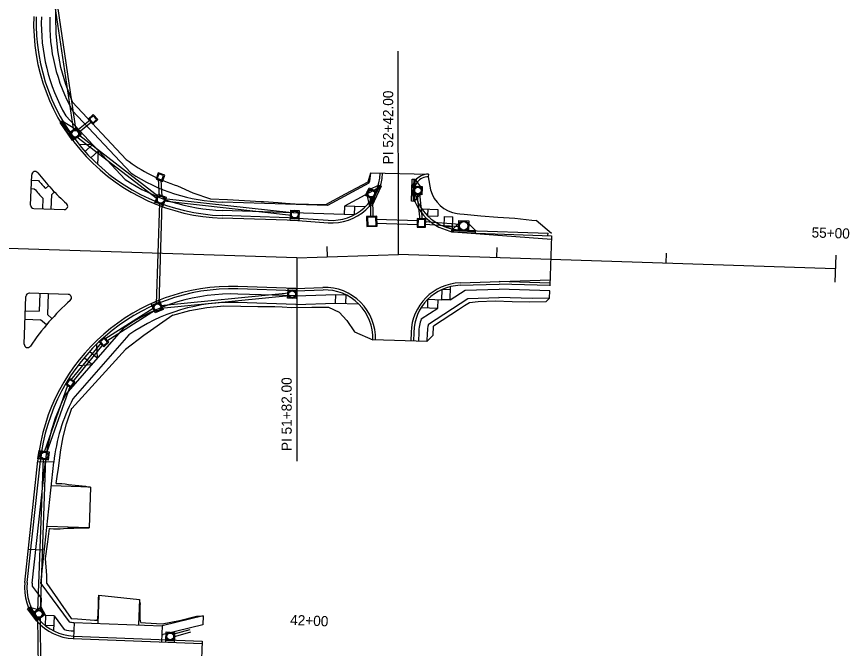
# Model space of a CAD drawing. Extents: x 979959 to 994833, y 1835619 to 1845316.
# Drawn here: x 992513.5 to 993004.9, y 1843149.5 to 1843522.3 of the extents above; entities that cross this region are included whole.
import ezdxf

# ---------------------------------------------------------------- set-up
doc = ezdxf.new("R2010")
doc.units = 0
for name, color, linetype in [('R_Drainage', 7, 'Continuous'), ('R_Horz Alg', 7, 'Continuous'), ('R_Horz Alg Annot', 7, 'Continuous'), ('R_Horz Alg Stationing', 7, 'Continuous'), ('R_Proposed Const Limits', 7, 'Continuous'), ('R_Proposed Road', 7, 'Continuous')]:
    doc.layers.add(name, color=color, linetype=linetype)

msp = doc.modelspace()

# ---------------------------------------------------------------- linework, layer by layer
at = {"layer": 'R_Drainage'}
for p, q in [((992526.47, 1843592.92), (992547.02, 1843454.89)), ((992527.95, 1843593.14), (992548.51, 1843455.11)), ((992540.06, 1843460.44), (992547.38, 1843449.69)), ((992540.47, 1843460.72), (992549.34, 1843455.3)), ((992556.85, 1843461.25), (992549.01, 1843454.92)), ((992557.86, 1843460.13), (992549.95, 1843453.75)), ((992548.7, 1843456.64), (992551.51, 1843452.51)), ((992549.97, 1843452.63), (992597.53, 1843415.96)), ((992549.05, 1843451.44), (992596.61, 1843414.78)), ((992597.04, 1843426.47), (992597.68, 1843416.04)), ((992598.58, 1843425.91), (992599.17, 1843416.13)), ((992727.32, 1843422.9), (992721.65, 1843420.09)), ((992722.28, 1843410.9), (992727.77, 1843422.69)), ((992748, 1843426.28), (992747.58, 1843413.29)), ((992748.5, 1843426.27), (992752.29, 1843421.2)), ((992719.44, 1843416.64), (992721.55, 1843421.17)), ((992748.08, 1843413.27), (992752.19, 1843418.08)), ((992749.74, 1843417.78), (992751.4, 1843402.56)), ((992751.24, 1843417.94), (992752.92, 1843402.51)), ((992752.87, 1843422.12), (992752.71, 1843417.12)), ((992597.1, 1843417.47), (992601.77, 1843415.68)), ((992675.72, 1843404.94), (992600.3, 1843413.29)), ((992675.72, 1843404.94), (992600.3, 1843413.29)), ((992675.88, 1843406.43), (992600.46, 1843414.78)), ((992675.88, 1843406.43), (992600.46, 1843414.78)), ((992721.82, 1843411.12), (992720.33, 1843417.26)), ((992722.05, 1843415.98), (992722.3, 1843403.92)), ((992723.55, 1843416.01), (992723.8, 1843403.98)), ((992597.73, 1843412.41), (992595.94, 1843352.57)), ((992597.73, 1843412.41), (992595.94, 1843352.57)), ((992599.23, 1843412.36), (992597.44, 1843352.53)), ((992599.23, 1843412.36), (992597.44, 1843352.53)), ((992675.23, 1843408.07), (992680.23, 1843407.89)), ((992750.42, 1843401.84), (992725.56, 1843402.62)), ((992750.34, 1843399.34), (992725.65, 1843400.12)), ((992774.9, 1843398.22), (992754.35, 1843399.64)), ((992775, 1843399.71), (992754.4, 1843401.14)), ((992770.25, 1843396.53), (992775.34, 1843401.04)), ((992784.25, 1843396.07), (992779.47, 1843400.91)), ((992770.24, 1843396.03), (992784.23, 1843395.57)), ((992674.14, 1843359.07), (992598.41, 1843351.62)), ((992674.14, 1843359.07), (992598.41, 1843351.62)), ((992674.29, 1843357.58), (992598.56, 1843350.13)), ((992674.29, 1843357.58), (992598.56, 1843350.13)), ((992678.42, 1843355.88), (992673.43, 1843356.15)), ((992594.67, 1843350.34), (992565.63, 1843331.91)), ((992595.47, 1843349.07), (992566.66, 1843330.78)), ((992599.92, 1843349.37), (992595.31, 1843347.42)), ((992563.42, 1843329.88), (992545.33, 1843307.71)), ((992564.44, 1843328.76), (992546.62, 1843306.92)), ((992543.75, 1843305.16), (992529.8, 1843265.3)), ((992545.06, 1843304.36), (992531.21, 1843264.81)), ((992532.69, 1843265.47), (992532.06, 1843260.51)), ((992529.08, 1843261.48), (992525.87, 1843171.69)), ((992530.58, 1843261.43), (992527.37, 1843171.64)), ((992520.65, 1843173.5), (992526.07, 1843166.31)), ((992521.05, 1843173.8), (992527.18, 1843172.24)), ((992527.05, 1843173.31), (992530.06, 1843169.32)), ((992525.83, 1843167.95), (992526.27, 1843128.53)), ((992527.33, 1843167.97), (992527.77, 1843128.47)), ((992601.76, 1843159.14), (992606.76, 1843158.94)), ((992605.74, 1843157.77), (992615.99, 1843160.69)), ((992606.15, 1843156.33), (992616.4, 1843159.25))]:
    msp.add_line(p, q, dxfattribs=at)
for points in [[(992558.38, 1843458.81), (992561.35, 1843461.48), (992558.67, 1843464.46), (992555.7, 1843461.78)], [(992558.41, 1843459.51), (992560.64, 1843461.52), (992558.64, 1843463.75), (992556.41, 1843461.74)], [(992540.47, 1843460.72), (992547.8, 1843449.98), (992546.56, 1843449.13), (992539.23, 1843459.87)], [(992548.7, 1843456.64), (992551.51, 1843452.51), (992547.38, 1843449.69), (992544.57, 1843453.83)], [(992600.88, 1843428.8), (992597.12, 1843430.16), (992595.76, 1843426.4), (992599.52, 1843425.04)], [(992600.24, 1843428.5), (992597.42, 1843429.52), (992596.4, 1843426.7), (992599.22, 1843425.68)], [(992721.82, 1843411.12), (992727.32, 1843422.9), (992728.68, 1843422.26), (992723.18, 1843410.48)], [(992748.5, 1843426.27), (992748.08, 1843413.27), (992746.58, 1843413.32), (992747, 1843426.32)], [(992719.44, 1843416.64), (992721.55, 1843421.17), (992726.08, 1843419.06), (992723.97, 1843414.53)], [(992752.87, 1843422.12), (992752.71, 1843417.12), (992747.71, 1843417.29), (992747.87, 1843422.29)], [(992595.49, 1843413.27), (992600.15, 1843411.47), (992599.62, 1843410.07), (992594.95, 1843411.87)], [(992597.1, 1843417.47), (992601.77, 1843415.68), (992599.97, 1843411.01), (992595.31, 1843412.8)], [(992675.23, 1843408.07), (992680.23, 1843407.89), (992680.05, 1843402.9), (992675.06, 1843403.07)], [(992675.08, 1843403.57), (992680.07, 1843403.4), (992680.02, 1843401.9), (992675.02, 1843402.07)], [(992726, 1843404.55), (992720, 1843404.35), (992720.2, 1843398.35), (992726.2, 1843398.55)], [(992725.51, 1843404.03), (992720.52, 1843403.86), (992720.69, 1843398.87), (992725.68, 1843399.04)], [(992754.96, 1843402.95), (992749.96, 1843403.11), (992749.8, 1843398.11), (992754.8, 1843397.95)], [(992754.44, 1843402.46), (992750.45, 1843402.59), (992750.32, 1843398.6), (992754.31, 1843398.47)], [(992774.43, 1843401.9), (992780.43, 1843401.7), (992780.23, 1843395.7), (992774.24, 1843395.9)], [(992770.25, 1843396.53), (992784.25, 1843396.07), (992784.2, 1843394.57), (992770.2, 1843395.03)], [(992678.42, 1843355.88), (992673.43, 1843356.15), (992673.7, 1843361.14), (992678.69, 1843360.87)], [(992678.66, 1843360.37), (992673.67, 1843360.64), (992673.75, 1843362.14), (992678.74, 1843361.87)], [(992598.16, 1843353.51), (992593.56, 1843351.56), (992592.97, 1843352.94), (992597.57, 1843354.89)], [(992599.92, 1843349.37), (992595.31, 1843347.42), (992593.36, 1843352.02), (992597.96, 1843353.97)], [(992564.91, 1843327.51), (992567.86, 1843330.21), (992565.16, 1843333.16), (992562.21, 1843330.46)], [(992564.94, 1843328.21), (992567.16, 1843330.24), (992565.13, 1843332.45), (992562.92, 1843330.43)], [(992545.85, 1843303.29), (992547.94, 1843306.7), (992544.53, 1843308.79), (992542.44, 1843305.38)], [(992545.69, 1843303.97), (992547.25, 1843306.53), (992544.7, 1843308.1), (992543.13, 1843305.54)], [(992528.23, 1843266.04), (992527.59, 1843261.08), (992526.1, 1843261.27), (992526.74, 1843266.23)], [(992532.69, 1843265.47), (992532.06, 1843260.51), (992527.1, 1843261.14), (992527.73, 1843266.1)], [(992521.05, 1843173.8), (992526.47, 1843166.61), (992525.27, 1843165.71), (992519.85, 1843172.9)], [(992527.05, 1843173.31), (992530.06, 1843169.32), (992526.07, 1843166.31), (992523.06, 1843170.31)], [(992601.76, 1843159.14), (992606.76, 1843158.94), (992606.57, 1843153.95), (992601.57, 1843154.14)], [(992601.59, 1843154.64), (992606.58, 1843154.45), (992606.53, 1843152.95), (992601.53, 1843153.14)]]:
    msp.add_lwpolyline(points, close=True, dxfattribs=at)
for centre, radius in [((992548.04, 1843453.17), 2.5), ((992548.04, 1843453.17), 2.5), ((992548.04, 1843453.17), 2), ((992548.04, 1843453.17), 2), ((992722.76, 1843417.85), 2.5), ((992722.76, 1843417.85), 2.5), ((992722.76, 1843417.85), 2), ((992722.76, 1843417.85), 2), ((992750.29, 1843419.7), 2.5), ((992750.29, 1843419.7), 2.5), ((992750.29, 1843419.7), 2), ((992750.29, 1843419.7), 2), ((992598.54, 1843414.24), 2.5), ((992598.54, 1843414.24), 2.5), ((992598.54, 1843414.24), 2), ((992598.54, 1843414.24), 2), ((992677.64, 1843405.48), 2.5), ((992677.64, 1843405.48), 2.5), ((992677.64, 1843405.48), 2), ((992677.64, 1843405.48), 2), ((992777.33, 1843398.8), 3), ((992777.33, 1843398.8), 3), ((992777.33, 1843398.8), 2.5), ((992777.33, 1843398.8), 2.5), ((992676.06, 1843358.51), 2.5), ((992676.06, 1843358.51), 2.5), ((992676.06, 1843358.51), 2), ((992676.06, 1843358.51), 2), ((992596.64, 1843350.7), 2.5), ((992596.64, 1843350.7), 2.5), ((992596.64, 1843350.7), 2), ((992596.64, 1843350.7), 2), ((992529.89, 1843263.31), 2.5), ((992529.89, 1843263.31), 2.5), ((992529.89, 1843263.31), 2), ((992529.89, 1843263.31), 2), ((992526.56, 1843169.81), 2.5), ((992526.56, 1843169.81), 2.5), ((992526.56, 1843169.81), 2), ((992526.56, 1843169.81), 2), ((992604.16, 1843156.54), 2.5), ((992604.16, 1843156.54), 2.5), ((992604.16, 1843156.54), 2), ((992604.16, 1843156.54), 2)]:
    msp.add_circle(centre, radius, dxfattribs=at)
at = {"layer": 'R_Horz Alg'}
for p, q in [((992678.8, 1843379.93), (992496.9, 1843385.9)), ((992678.8, 1843379.93), (992738.77, 1843381.96)), ((992996.63, 1843373.5), (992738.77, 1843381.96))]:
    msp.add_line(p, q, dxfattribs=at)
at = {"layer": 'R_Horz Alg Annot'}
for points in [[(992738.77, 1843381.96), (992738.7, 1843501.96)], [(992678.8, 1843379.93), (992678.87, 1843259.93)]]:
    msp.add_lwpolyline(points, dxfattribs=at)
at = {"layer": 'R_Horz Alg Stationing'}
for points in [[(992597.04, 1843388.62), (992596.85, 1843382.62)], [(992696.59, 1843386.54), (992696.79, 1843380.54)], [(992796.93, 1843386.06), (992796.74, 1843380.06)], [(992896.88, 1843382.78), (992896.68, 1843376.78)], [(992996.89, 1843381.49), (992996.36, 1843365.5)]]:
    msp.add_lwpolyline(points, dxfattribs=at)
at = {"layer": 'R_Proposed Const Limits'}
for p, q in [((992546.49, 1843471.84), (992578.15, 1843437.98)), ((992756.47, 1843427.76), (992757.74, 1843420.14)), ((992608.5, 1843422.41), (992617.57, 1843418.38))]:
    msp.add_line(p, q, dxfattribs=at)
for points in [[(992546.49, 1843471.84), (992546.39, 1843472.05), (992542.46, 1843482.19), (992539.58, 1843492.3), (992537.77, 1843502.36), (992536.93, 1843512.4), (992536.66, 1843522.41), (992536.52, 1843532.42), (992536.43, 1843542.43), (992536.26, 1843552.45), (992536.22, 1843554.46), (992536.31, 1843562.45), (992535.91, 1843572.47), (992535.73, 1843577.99), (992535.61, 1843582.49), (992535.74, 1843592.49), (992538.25, 1843608.43)], [(992696, 1843411.44), (992707.64, 1843417.7), (992720.98, 1843424.82), (992722.47, 1843430.02)], [(992617.57, 1843418.38), (992627.91, 1843414.69), (992637.91, 1843414.36), (992647.89, 1843413.73), (992657.88, 1843413.2), (992659.13, 1843413.22), (992667.87, 1843412.55), (992672.25, 1843412.21), (992677.85, 1843411.84), (992677.85, 1843411.84), (992685.73, 1843411.61), (992695.16, 1843411.45), (992696, 1843411.44)], [(992773.55, 1843406.12), (992775.15, 1843405.91), (992777.57, 1843405.68), (992787.54, 1843404.8), (992797.52, 1843404.02), (992807.5, 1843403.33), (992817.47, 1843402.19), (992820.11, 1843401.95)], [(992829.22, 1843394.34), (992820.11, 1843401.95)], [(992827.97, 1843356.1), (992825.9, 1843354.03), (992815.89, 1843353.87), (992805.89, 1843354.06), (992795.89, 1843354.34), (992785.87, 1843353.89), (992780.77, 1843353.46), (992777.89, 1843351.65), (992774.25, 1843349.28), (992769.78, 1843346.36), (992759.59, 1843339.71)], [(992605.65, 1843346.18), (992615.75, 1843348.86), (992625.81, 1843350.7), (992635.85, 1843351.66), (992645.85, 1843351.39), (992655.85, 1843351.26), (992657.1, 1843351.26), (992665.85, 1843351.13), (992670.24, 1843350.95), (992675.84, 1843350.73), (992675.85, 1843350.73), (992687.79, 1843350.83), (992697.21, 1843350.82), (992697.6, 1843350.82)], [(992697.6, 1843350.82), (992703.81, 1843347.92), (992708.41, 1843342.89), (992712.83, 1843336.28), (992723.8, 1843331.55)], [(992605.65, 1843346.18), (992588.49, 1843334.03), (992577.81, 1843325.85), (992545.98, 1843291.08)], [(992755.68, 1843330.48), (992759.41, 1843334.33), (992759.59, 1843339.71)], [(992536.74, 1843246.76), (992537.6, 1843252.22), (992538.13, 1843255.65), (992538.9, 1843262.18), (992539.51, 1843266.63), (992540.51, 1843272.14), (992540.96, 1843274.25), (992542.97, 1843282.06), (992546.04, 1843291.15)], [(992536.74, 1843246.76), (992538.16, 1843246.8), (992540.15, 1843246.71), (992542.15, 1843246.48), (992544.14, 1843246.26), (992546.13, 1843246.04), (992548.13, 1843245.82), (992550.12, 1843245.6), (992552.12, 1843245.38), (992554.11, 1843245.15), (992555.59, 1843244.82), (992557.09, 1843244.55)], [(992531.41, 1843187.85), (992531.27, 1843192.41), (992530.53, 1843202.44), (992531.9, 1843212.4), (992532.95, 1843220.18)], [(992532.95, 1843220.18), (992533.24, 1843220.17), (992535.24, 1843220.08), (992537.24, 1843219.98), (992539.24, 1843220.04), (992541.25, 1843220.23), (992543.25, 1843220.32), (992545.26, 1843220.39), (992547.26, 1843220.47), (992549.26, 1843220.55), (992551.27, 1843220.63), (992556.27, 1843220.56)], [(992531.41, 1843187.85), (992545.67, 1843167.2), (992549.52, 1843166.89), (992559.5, 1843166.15), (992561.25, 1843166.05)], [(992561.6, 1843169.69), (992561.66, 1843171.69), (992561.72, 1843173.69), (992561.78, 1843175.69), (992561.84, 1843177.69), (992561.87, 1843178.69), (992562.07, 1843180.85)], [(992586.71, 1843164.71), (992586.71, 1843164.72), (992586.47, 1843166.73), (992586.38, 1843168.74), (992586.38, 1843170.74), (992586.45, 1843173.74), (992586.47, 1843174.74), (992586.56, 1843175.51), (992585.99, 1843178.39)], [(992561.25, 1843166.05), (992561.51, 1843167.7), (992561.6, 1843169.69)], [(992586.71, 1843164.71), (992589.46, 1843164.56), (992599.45, 1843163.99), (992609.53, 1843165.96), (992619.64, 1843168.57), (992623.64, 1843168.59)]]:
    msp.add_lwpolyline(points, dxfattribs=at)
for centre, radius, start, end in [((992638.52, 1843518.33), 100.5, 233.0801, 252.6206), ((992776.12, 1843424.95), 19, 194.6721, 262.2107)]:
    msp.add_arc(centre, radius, start, end, dxfattribs=at)
at = {"layer": 'R_Proposed Road'}
for p, q in [((992542.47, 1843463.69), (992577.56, 1843426.16)), ((992546.53, 1843466.67), (992580.81, 1843430.01)), ((992550.21, 1843447.02), (992558.31, 1843446.75)), ((992558.31, 1843446.75), (992553.93, 1843442.65)), ((992561.73, 1843443.1), (992557.34, 1843439)), ((992561.46, 1843435), (992561.73, 1843443.1)), ((992521.78, 1843411.1), (992522.39, 1843428.96)), ((992722.48, 1843430.02), (992722.47, 1843429.84)), ((992722.47, 1843430.02), (992756.51, 1843429.25)), ((992756.51, 1843429.25), (992756.47, 1843427.76)), ((992522.28, 1843425.76), (992526.33, 1843425.62)), ((992721.45, 1843423.94), (992696.95, 1843410.85)), ((992522.11, 1843420.77), (992523.95, 1843420.7)), ((992532.38, 1843422.5), (992530.54, 1843420.79)), ((992535.79, 1843418.85), (992534.02, 1843417.19)), ((992726.3, 1843420.86), (992706.95, 1843410.52)), ((992528.95, 1843415.15), (992528.75, 1843408.87)), ((992534.02, 1843417.19), (992533.74, 1843408.71)), ((992696.95, 1843410.85), (992635.06, 1843412.88)), ((992523.71, 1843409.04), (992541.57, 1843408.45)), ((992712.78, 1843405.33), (992634.89, 1843407.89)), ((992706.95, 1843410.52), (992706.78, 1843405.53)), ((992719.36, 1843410.12), (992706.95, 1843410.52)), ((992712.94, 1843410.33), (992712.78, 1843405.33)), ((992752.55, 1843408.93), (992762.14, 1843408.54)), ((992756.15, 1843408.78), (992755.98, 1843404.79)), ((992762.14, 1843408.54), (992761.98, 1843404.54)), ((992679.52, 1843401.92), (992634.75, 1843403.39)), ((992679.57, 1843403.42), (992634.8, 1843404.89)), ((992679.63, 1843403.41), (992697.42, 1843402.12)), ((992755.98, 1843404.78), (992761.98, 1843404.54)), ((992765.81, 1843398.38), (992766.01, 1843404.38)), ((992766.01, 1843404.38), (992771, 1843404.21)), ((992770.76, 1843396.96), (992771, 1843404.21)), ((992679.52, 1843401.92), (992697.31, 1843400.62)), ((992765.81, 1843398.38), (992770.81, 1843398.22)), ((992773.94, 1843395.03), (992829.11, 1843391)), ((992774.05, 1843396.53), (992779.43, 1843396.14)), ((992779.25, 1843394.64), (992829.18, 1843393)), ((992779.43, 1843396.14), (992827.1, 1843394.57)), ((992827.06, 1843393.07), (992827.1, 1843394.57)), ((992829.18, 1843393), (992828.21, 1843363.48)), ((992775.29, 1843365.22), (992828.32, 1843367.02)), ((992775.34, 1843363.72), (992798.3, 1843364.5)), ((992828.26, 1843365.02), (992798.3, 1843366)), ((992828.21, 1843363.52), (992798.3, 1843364.5)), ((992543.92, 1843358.34), (992520.99, 1843359.1)), ((992527.1, 1843358.9), (992526.76, 1843348.39)), ((992532.1, 1843358.73), (992531.7, 1843346.46)), ((992678.16, 1843360.44), (992644.07, 1843361.56)), ((992678.21, 1843361.94), (992644.12, 1843363.06)), ((992678.21, 1843361.94), (992694.3, 1843362.48)), ((992678.26, 1843360.44), (992694.35, 1843360.98)), ((992764.39, 1843355.22), (992764.59, 1843361.22)), ((992769.59, 1843361.06), (992764.59, 1843361.22)), ((992769.39, 1843355.06), (992769.65, 1843362.95)), ((992769.39, 1843355.06), (992778.22, 1843360.82)), ((992778.22, 1843360.82), (992798.3, 1843361.5)), ((992828.11, 1843360.52), (992798.2, 1843361.5)), ((992827.97, 1843356.1), (992828.11, 1843360.52)), ((992517.96, 1843329.01), (992518.93, 1843357.17)), ((992678.21, 1843357.44), (992643.98, 1843358.56)), ((992678.21, 1843357.44), (992701.94, 1843358.24)), ((992701.77, 1843353.24), (992701.94, 1843358.24)), ((992701.94, 1843358.24), (992707.93, 1843358.04)), ((992707.77, 1843353.05), (992707.93, 1843358.04)), ((992756.09, 1843350.49), (992756.25, 1843355.49)), ((992756.25, 1843355.49), (992764.39, 1843355.22)), ((992756.55, 1843340.72), (992779.79, 1843355.87)), ((992762.08, 1843350.3), (992762.25, 1843355.29)), ((992769.39, 1843355.06), (992764.39, 1843355.22)), ((992779.79, 1843355.87), (992798.31, 1843356.5)), ((992817.95, 1843355.85), (992798.04, 1843356.5)), ((992827.95, 1843356.1), (992817.95, 1843355.85)), ((992678.21, 1843352.43), (992643.81, 1843353.56)), ((992678.21, 1843352.43), (992701.77, 1843353.23)), ((992701.77, 1843353.24), (992715.32, 1843352.8)), ((992752.31, 1843350.62), (992762.08, 1843350.3)), ((992752.34, 1843343.94), (992762.08, 1843350.3)), ((992518.64, 1843348.67), (992526.76, 1843348.39)), ((992534.37, 1843344.13), (992531.7, 1843346.46)), ((992518.46, 1843343.67), (992527.66, 1843343.35)), ((992531.08, 1843340.36), (992527.66, 1843343.35)), ((992576.36, 1843338.21), (992542.54, 1843299.53)), ((992579.73, 1843334.47), (992546.7, 1843296.69)), ((992746.32, 1843335.98), (992746.19, 1843330.8)), ((992747.82, 1843335.94), (992747.69, 1843330.76)), ((992750.82, 1843335.87), (992750.69, 1843330.69)), ((992755.81, 1843335.74), (992755.68, 1843330.48)), ((992755.68, 1843330.48), (992723.8, 1843331.55)), ((992561.1, 1843320.75), (992556.58, 1843324.7)), ((992560.55, 1843328.84), (992561.1, 1843320.75)), ((992557.8, 1843316.99), (992553.29, 1843320.94)), ((992549.72, 1843316.45), (992557.8, 1843316.99)), ((992518.29, 1843188.43), (992526.01, 1843260.39)), ((992519.78, 1843188.27), (992527.5, 1843260.23)), ((992522.76, 1843187.95), (992530.48, 1843259.91)), ((992535.44, 1843259.3), (992525.92, 1843259.63)), ((992527.77, 1843187.73), (992535.45, 1843259.37)), ((992557.09, 1843244.55), (992534.02, 1843245.34)), ((992557.09, 1843244.55), (992556.27, 1843220.56)), ((992556.27, 1843220.56), (992531.45, 1843221.42)), ((992529.88, 1843207.46), (992520.36, 1843207.79)), ((992527.77, 1843187.73), (992544.53, 1843165.04)), ((992522.64, 1843186.26), (992527.99, 1843179.01)), ((992527.99, 1843179.01), (992527.82, 1843174.01)), ((992562.07, 1843180.85), (992561.43, 1843164.2)), ((992562.07, 1843180.85), (992585.99, 1843178.39)), ((992585.99, 1843178.39), (992585.41, 1843163.27)), ((992527.82, 1843174.01), (992530.59, 1843168.93)), ((992530.59, 1843168.93), (992530.36, 1843162.94)), ((992535.58, 1843168.74), (992530.59, 1843168.93)), ((992535.58, 1843168.74), (992535.24, 1843159.8)), ((992535.58, 1843168.74), (992541.62, 1843160.57)), ((992623.64, 1843168.59), (992599.4, 1843162.73)), ((992623.64, 1843168.59), (992623.44, 1843163.4)), ((992535.35, 1843162.74), (992530.36, 1843162.94)), ((992547.44, 1843164.74), (992547.07, 1843155.25)), ((992547.32, 1843164.74), (992599.4, 1843162.73)), ((992599.4, 1843162.73), (992599.03, 1843153.24)), ((992623.44, 1843163.4), (992599.9, 1843157.71)), ((992547.13, 1843159.75), (992547.25, 1843159.74)), ((992599.21, 1843157.73), (992599.9, 1843157.71)), ((992546.96, 1843155.25), (992623.01, 1843152.31)), ((992547.01, 1843156.75), (992623.07, 1843153.81)), ((992623.07, 1843153.81), (992621.44, 1843111.51))]:
    msp.add_line(p, q, dxfattribs=at)
for centre, radius, start, end in [((992638.52, 1843518.33), 115, 178.0361, 268.1194), ((992638.52, 1843518.33), 113.5, 178.0361, 268.1194), ((992638.52, 1843518.33), 110.5, 178.0361, 209.6347), ((992638.52, 1843518.33), 105.5, 178.0361, 209.3184), ((992524.39, 1843428.89), 2, 38.0831, 178.0361), ((992638.52, 1843518.33), 143, 218.0831, 228.0725), ((992638.52, 1843518.33), 105.5, 236.8372, 268.1194), ((992699.49, 1843430.54), 30, 265.8268, 358.7075), ((992699.49, 1843430.54), 28.5, 265.8268, 358.7075), ((992701.98, 1843430.36), 20.5, 341.7549, 358.5567), ((992756.29, 1843419.76), 9.5, 88.7075, 194.6721), ((992756.29, 1843419.76), 8, 88.7075, 194.6721), ((992638.54, 1843519.03), 146, 219.7747, 222.2917), ((992638.52, 1843518.33), 110.5, 236.5208, 268.1194), ((992638.54, 1843519.03), 151, 220.6303, 223.4662), ((992776.12, 1843424.95), 28.5, 194.6721, 265.8268), ((992776.12, 1843424.95), 30, 194.6721, 265.8268), ((992523.78, 1843411.03), 2, 178.0361, 268.1194), ((992541.63, 1843410.45), 2, 268.1194, 48.0725), ((992776.31, 1843335.24), 30, 91.9369, 178.589), ((992776.31, 1843335.24), 28.5, 91.9369, 178.589), ((992520.93, 1843357.1), 2, 88.1194, 178.0361), ((992640.35, 1843248.12), 115, 88.1194, 173.8765), ((992640.35, 1843248.12), 113.5, 88.1194, 173.8765), ((992695.32, 1843332.5), 30, 358.0857, 91.9369), ((992695.32, 1843332.5), 28.5, 358.0857, 91.9369), ((992640.35, 1843248.12), 143, 131.7223, 146.1268), ((992543.85, 1843356.35), 2, 311.7223, 88.1194), ((992640.35, 1843248.12), 110.5, 88.1194, 125.3859), ((992640.35, 1843248.12), 105.5, 88.1194, 125.0696), ((992776.31, 1843335.24), 25.5, 160.0559, 178.589), ((992776.31, 1843335.24), 20.5, 164.4998, 178.589), ((992519.96, 1843328.94), 2, 178.0361, 326.1268), ((992640.35, 1843248.12), 110.5, 152.272, 173.8765), ((992640.35, 1843248.12), 105.5, 152.5884, 173.8765), ((992548.11, 1843185.23), 30, 173.8765, 267.7861), ((992548.11, 1843185.23), 28.5, 173.8765, 267.7861), ((992548.11, 1843185.23), 25.5, 173.8765, 177.675), ((992548.11, 1843185.23), 20.5, 259.9356, 267.7861), ((992548.11, 1843185.23), 25.5, 255.2493, 267.7861)]:
    msp.add_arc(centre, radius, start, end, dxfattribs=at)

# ---------------------------------------------------------------- texts
at = {"layer": 'R_Horz Alg Annot'}
for s, p in [('PI 52+42.00', (992735.74, 1843435.13)), ('PI 51+82.00', (992675.86, 1843265.93))]:
    msp.add_text(s, height=6, rotation=90.0307, dxfattribs=at).set_placement(p)
at = {"layer": 'R_Horz Alg Stationing'}
for s, rotation, p in [('55+00', 358.1194, (992982.58, 1843391.97)), ('42+00', 357.7861, (992674.83, 1843163.32))]:
    msp.add_text(s, height=6, rotation=rotation, dxfattribs=at).set_placement(p)

doc.saveas('drawing.dxf')
